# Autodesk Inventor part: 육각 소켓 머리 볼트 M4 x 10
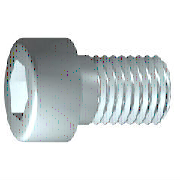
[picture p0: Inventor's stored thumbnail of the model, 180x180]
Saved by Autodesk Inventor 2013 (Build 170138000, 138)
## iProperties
IsCustomPart: 1
Created: 2012-02
Part Number: 육각 소켓 머리 볼트 M4 x 10
Material: 스테인리스강
Description: 6각 소켓 머리 캡 나사
Document SubType Name: Modeling
Standard: ISO 4762
Designer: mduedu
Standard Revision: Fourth edition 2004-03-01
Standards Organization: ISO
Language: ko-KR
Size Designation: M4 x 10
Categories: <MemberInstance><Categories><Category DisplayName="조임쇠" InternalName="e4da775c-781d-43d5-af7c-5136215cf5a6" Mnemonic="FSTN"><Category DisplayName="볼트" InternalN
Density: 7.75 g/cm^3
Mass: 2.0086 g
Surface Area: 3.0572 cm^2
Volume: 0.259174 cm^3
Author: mduedu
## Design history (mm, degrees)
sketch "스케치1"
  geometry: L1 (-1, 0)-(10, 0); L2 (10, 0)-(10, 2); L3 (10, 2)-(1.75, 2); L4 (1.75, 2)-(1.32, 2); L5 (1.32, 2)-(0, 2); L6 (0, 2)-(0, 3.5); L7 (0, 3.5)-(-4, 3.5); L8 (-4, 3.5)-(-4, 1.732); L9 (-4, 1.732)-(-2, 1.732); L10 (-2, 1.732)-(-1, 0); L11 (-6.8, 0)-(12.8, 0) reference; L12 (0, -0.7)-(0, 4.2) reference; L13 (1.75, 2)-(0, 2)
  constraints: 22 end point, 6 parallel, 2 collinear, 2 perpendicular, 1 horizontal, 1 point on line
  dimensions: "d1" = 8.25 distance from line of L3.end L2 (= GEL); "d2" = 0.42952 distance of L4.end L3.end (computed from GAL); "d3" = 4 distance between parallel lines of L8 L6 (= KOH); "d4" = 2 distance of L8.end L9.end (= INTI); "d5" = 60 deg angle of L10 L1; "d6" = 4 diameter of L3 L1 (= GD); "d7" = 4 diameter of L5 L1 (= BDM); "d8" = 3.4641 diameter of L9 L1 (= 1.1547 x SW); "d9" = 7 diameter of L7 L1 (= KOD); "d26" = 10 distance between parallel lines of L12 L2 (= NLG)
revolve "본체" sketch "스케치1" stored, may be unused: angle "d10" = 90 deg
sketch "스케치2"
  geometry: L1 (0, -4.9)-(0, 4.9) reference; L2 (-4.9, 0)-(4.9, 0) reference; L3 (1.732, 0)-(0.866, -1.5); L4 (0.866, -1.5)-(-0.866, -1.5); L5 (-0.866, -1.5)-(-1.732, 0); L6 (-1.732, 0)-(-0.866, 1.5); L7 (-0.866, 1.5)-(0.866, 1.5); L8 (0.866, 1.5)-(1.732, 0); 2 further points
  constraints: 12 end point, 1 coincident, 1 horizontal alignment, 1 point on line, 12 other
extrude "슬롯" join sketch "스케치2" stored distance "d11" = 10; taper "d12" = 0 deg
workplane "Work Plane1"
fillet "Fillet2" dims "d30" = 0.1 (= R)
body "Solid1"
fillet "모깎기1" dims "d17" = 0.4 (= RR)
feature "스레드" dims "d13" = 8.25 (= GEL), "d14" = 0
chamfer "모따기1" distance "d15" = 0.42941 (= -0.5 x SPD + 0.5 x GD); stored, may be unused: second distance "d16" = 0.42941 (= GUL), angle "d27" = 45 deg
other parameters: "GD" = 4 [user parameter; used in 2 equation terms], "NLG" = 10 [user parameter; used in 1 equation term], "GEL" = 8.25 [user parameter; used in 2 equation terms], "KOD" = 7 [user parameter; used in 1 equation term], "KOH" = 4 [user parameter; used in 1 equation term], "INTI" = 2 [user parameter; used in 1 equation term], "GAL" = 0.42941 (= 0.61345 x PTC) [user parameter; used in 1 equation term], "GUL" = 0.42941 (= 0.61345 x PTC) [user parameter; used in 1 equation term], "BDM" = 4 (= NND) [user parameter; used in 1 equation term], "SW" = 3 [user parameter; used in 2 equation terms], "RR" = 0.4 [user parameter; used in 1 equation term], "SPD" = 3.14117 (= NND - 1.2269 x PTC) [user parameter; used in 1 equation term], "d19" = 0, "d28" = 0, "d29" = 0, "R" = 0.1 [user parameter; used in 1 equation term], "TOA" = 30 deg [user parameter], "GD1" = 3.14117 (= THREADDIA - 1.2269 x PTC) [user parameter], "THREADDIA" = 4 [user parameter; used in 1 equation term], "FAWI" = 45 deg [user parameter], "TPU" = 14.28571 (computed from PTC) [user parameter], "PTC" = 0.7 [user parameter; used in 5 equation terms], "NND" = 4 [user parameter; used in 2 equation terms], "E0" = 3.465 (= 1.155 x SW) [user parameter]
